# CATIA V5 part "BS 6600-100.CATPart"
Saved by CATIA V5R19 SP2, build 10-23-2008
Part number: BS 6600-100
Bounding box of the stored display mesh (mm): x -59.975 to 59.975, y -59.975 to 59.975, z 0 to 275
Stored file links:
  C:\Users\Bora\Desktop\3D Katı model\BS serisi\BS 6600\BS 6600-100.CATPart
  C:\Program Files\Dassault Systemes\B19\intel_a\reffiles\standard\MetricThickPitch.txt
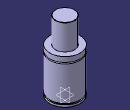
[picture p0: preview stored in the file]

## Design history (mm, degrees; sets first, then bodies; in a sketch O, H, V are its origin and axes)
Body1 (main body)
  Sketch1 on yz-plane, origin (0, 0, 0), H (0, 1, 0), V (0, 0, 1)
    point P1 (60, 154)
    point P2 (60, 149)
    point P3 (60, 154)
    point P7 (37.5, 274)
    point P9 (37.5, 274)
    point P14 (60, 149)
    arc A1 centre (60, 151.5) radius 2.5 from (60, 154) to (60, 149) ccw
    line L1 (60, 154) -> (60, 174)
    line L2 (60, 0) -> (60, 8)
    arc A2 centre (36.5, 274) radius 1 from (37.5, 274) to (36.5, 275) ccw
    line L3 (37.5, 274) -> (37.5, 174)
    line L4 (56, 13) -> (56, 8)
    line L5 (60, 13) -> (60, 149)
    line L6 (36.5, 275) -> (0, 275)
    point P15 (0, 275)
    line L7 (37.5, 174) -> (60, 174)
    line L8 (0, 0) -> (60, 0)
    line L9 (56, 13) -> (60, 13)
    line L10 (56, 8) -> (60, 8)
    coincidence: P15 V, P1 P3, P2 P14, P7 P9
    tangency: L6 A2
    horizontal: L7 H, L8 H, L9 H, L10 H
  Shaft1: profile Sketch1, axis Sketch1.V, angle 360
  Sketch2 on face of Shaft1 from Sketch1.L8, origin (0, 0, 0), H (1, 0, 0), V (0, -1, 0)
    point P1 (40, 0)
    distance P1 V = 40
  Hole1: placed by Sketch2, at (40, 0, 0) direction (0, 0, 1), diameter 8.376, depth 8, threaded "M10", thread diameter 10, thread depth 8, pitch 1.5
  CircPattern1: of Hole1, instances 4, angular step 90, axis from xy-plane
